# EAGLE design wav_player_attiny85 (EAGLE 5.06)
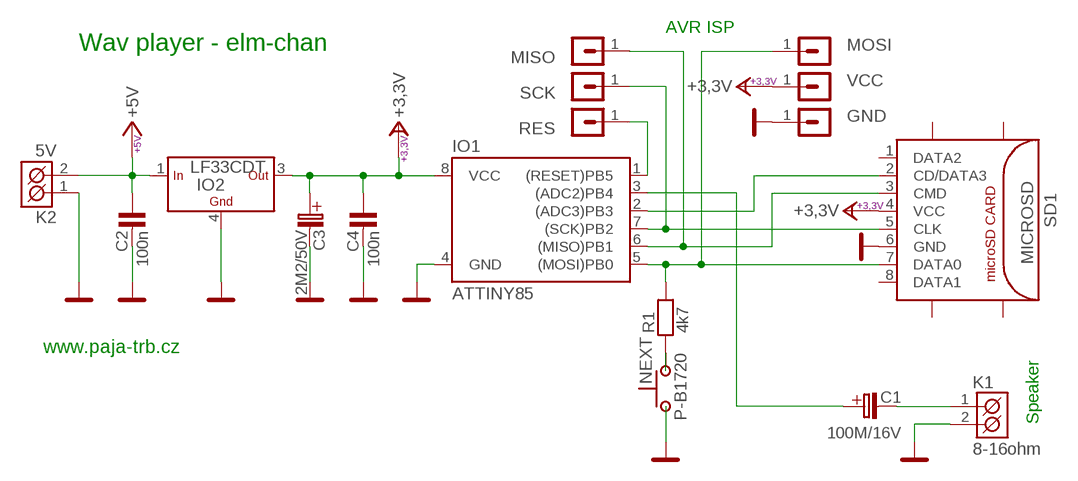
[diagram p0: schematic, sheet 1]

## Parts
C1  100M/16V  [C_EL_2,5]
C2  100n  C-KERAMIK_SMD_1206  [1206]
C3  2M2/50V  [C_EL_2]
C4  100n  C-KERAMIK_7,5  [C-7,5]
GND  S1G1_JUMP  [S1G1_JUM]
IO1  ATTINY85  ATTINY13  [SOIC08]
IO2  LF33CDT  LFDPAKDPAKC  [DPAK]
K1  8-16ohm  ARK550/2  [ARK550/2]
K2  5V  ARK550/2  [ARK550/2]
MISO  S1G1_JUMP  [S1G1_JUM]
MOSI  S1G1_JUMP  [S1G1_JUM]
NEXT  P-B1720  [P-B1720]
R1  4k7  R_SMD_1206  [1206]
RES  S1G1_JUMP  [S1G1_JUM]
SCK  S1G1_JUMP  [S1G1_JUM]
SD1  MICROSD  [MICRO_SD_CONNECTOR]
VCC  S1G1_JUMP  [S1G1_JUM]

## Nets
+3,3V: C3.C+(C_EL+) C4.1 IO1.8(VCC) IO2.3(OUT) SD1.4(VCC) VCC.1
+5V: C2.1 IO2.1(IN) K2.2(K2)
GND: C2.2 C3.C-(C_EL-) C4.2 GND.1 IO1.4(GND) IO2.4(GND) K1.2(K2) K2.1(K1) NEXT.1 NEXT.3 SD1.6(GND)
MISO: IO1.6((MISO)PB1) MISO.1 SD1.3(CMD)
MOSI: IO1.5((MOSI)PB0) MOSI.1 R1.2 SD1.7(DATA0)
N$1: C1.C-(C_EL-) K1.1(K1)
N$2: IO1.2((ADC3)PB3) SD1.2(CD/DATA3)
N$3: C1.C+(C_EL+) IO1.3((ADC2)PB4)
N$5: NEXT.2 NEXT.4 R1.1
RES: IO1.1((RESET)PB5) RES.1
SCK: IO1.7((SCK)PB2) SCK.1 SD1.5(CLK)
Unconnected: SD1.1(DATA2) SD1.8(DATA1) SD1.11(CD(1)) SD1.12(CD(2)) SD1.13(CD(3)) SD1.14(CD(4))

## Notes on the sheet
- AVR ISP
- Wav player - elm-chan
- www.paja-trb.cz
- Speaker

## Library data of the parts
C1 = #PaJa_C-el_2:100M/16V
C2 C4 = #PaJa_31:C-KERAMIK: Kondenzator - keramicky
C3 = #PaJa_C-el_2:2M2/50V
GND MISO MOSI RES SCK VCC = #PaJa_konektory:S1G1_JUMP: Radove konektory - koliky - 1x
IO1 = #PaJa_31:ATTINY13: ATMEL ATtiny 13
IO2 = #PaJa_31:LF??C: LF??C - stabilizátory low-drop výstup dle typu 1,25 - 12V
K1 K2 = #PaJa_konektory:ARK550/2: Svorkovnice - roztec 3,5mm - dvojita
NEXT = #PaJa_prepinace:P-B1720: &micro;-tlacitko
R1 = #PaJa_31:R: Rezistor
SD1 = #PaJa_konektory:MICROSD: MicroSD socked 112C-TXAR-R01 Attend technology

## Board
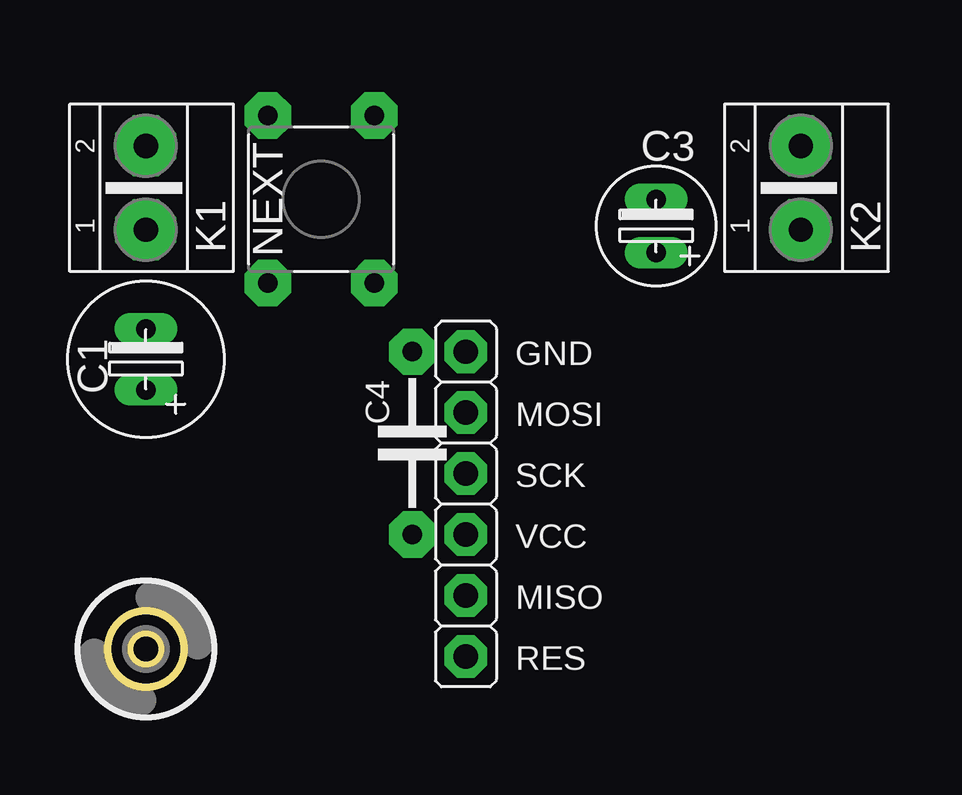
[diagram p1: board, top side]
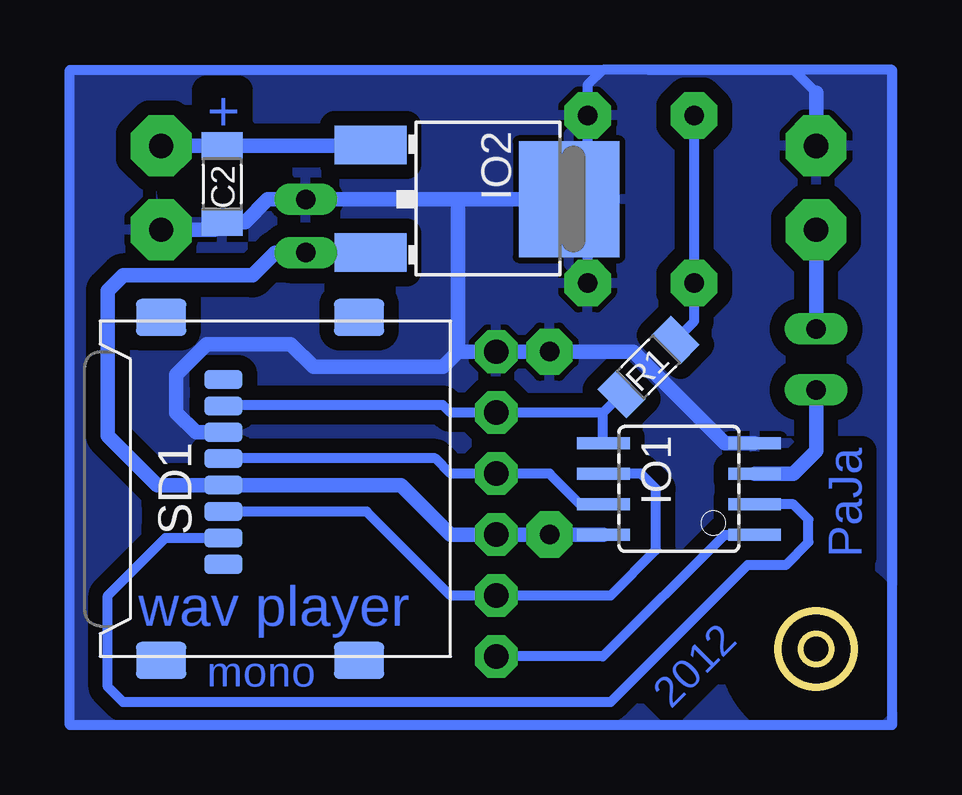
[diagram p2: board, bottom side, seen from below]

Size 3.17 x 3.17 mm. Coordinates in mm from the lower left corner, seen from the top.
Copper layers (1*16): Top 0.035mm / dielectric 1.5mm / Bottom 0.035mm
Design rules "default": minimum track width 10mil, minimum drill 24mil, track to track 8mil, track to pad 8mil, pad to pad 8mil, via to via 8mil, smd to smd 8mil, copper to edge 40mil, drill to drill 8mil, minimum pad ring 10mil, minimum via ring 8mil, stop-mask expansion 4mil, vias tented up to drill 0mil, thermal gap 10mil
bRestrict: 3 lines

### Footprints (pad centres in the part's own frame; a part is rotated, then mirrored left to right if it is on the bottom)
C_EL_2,5 = drill 0.813 pad 1.27 long: C+ -1.27,0; C- 1.27,0
1206 = smd 1.143 x 1.702: 1 -1.587,0; 2 1.587,0
C_EL_2 = drill 0.813 pad 1.27 long: C+ 0,0; C- 2.223,0
C-7,5 = drill 0.813 pad 1.93 octagon: 1 -3.81,0; 2 3.81,0
S1G1_JUM = drill 1.016 pad 1.778 octagon: 1 0,0
SOIC08 = smd 2.2 x 0.5: 1 -3.154,1.905; 2 -3.154,0.645; 3 -3.154,-0.625; 4 -3.154,-1.895; 5 3.154,-1.905; 6 3.154,-0.635; 7 3.154,0.635; 8 3.154,1.905
DPAK = smd 1.6 x 2.997: 1 -2.261,-4.928; 3 2.21,-4.928 | smd 4.826 x 4.191: 4 0,3.353
ARK550/2 = drill 1.016 pad 2.54 octagon: 1 0,0; 2 3.493,0
P-B1720 = drill 0.813 pad 1.93 octagon: 1 -3.493,-2.223; 2 -3.493,2.223; 3 3.493,-2.223; 4 3.493,2.223
MICRO_SD_CONNECTOR = smd 0.8 x 1.6: 1 -3.141,1.215; 2 -2.041,1.215; 3 -0.941,1.215; 4 0.159,1.215; 5 1.259,1.215; 6 2.359,1.215; 7 3.459,1.215; 8 4.559,1.215 | smd 1.55 x 2.1: 11 -7.144,3.81; 12 -7.144,-4.445; 13 7.144,-4.445; 14 7.144,3.81
HOLE_3,0 = hole 3.2: 0,0

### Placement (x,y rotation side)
C1  1.59,13.65 90 top  (outside the outline)
C2  26.35,20.96 270 bottom  (outside the outline)
C3  22.86,18.1 90 top  (outside the outline)
C4  12.7,10.16 90 top  (outside the outline)
GND  14.92,13.97 0 top  (outside the outline)
IO1  7.3,8.25 180 bottom  (outside the outline)
IO2  15.24,20.32 270 bottom  (outside the outline)
K1  1.59,19.05 90 top  (outside the outline)
K2  28.89,19.05 90 top  (outside the outline)
MISO  14.92,3.81 0 top  (outside the outline)
MOSI  14.92,11.43 0 top  (outside the outline)
NEXT  8.89,20.32 90 top  (outside the outline)
R1  8.57,13.33 225 bottom  (outside the outline)
RES  14.92,1.27 0 top  (outside the outline)
SCK  14.92,8.89 0 top  (outside the outline)
SD1  25.08,8.25 90 bottom  (outside the outline)
U$2  [HOLE_3,0]  1.59,1.59 0 top
VCC  14.92,6.35 0 top  (outside the outline)

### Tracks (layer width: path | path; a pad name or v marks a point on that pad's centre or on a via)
+3,3V
  Bottom 0.406: IO1.8 C4.1 | IO2.3 20.18,18.1
  Bottom 0.61: IO1.8 C4.1 VCC.1 16.83,6.35 18.89,8.41 SD1.4 29.05,8.41 31.12,10.48 31.12,16.51 30.48,17.15 25.08,17.15 24.13,18.1 C3.C+ 20.18,18.1
+5V
  Bottom 0.406: IO2.1 arc90 20.21,22.54
  Bottom 0.61: K2.2 C2.1 20.21,22.54
GND
  Bottom 0.406: IO1.4 | C2.2 arc90 26.67,19.05 | 11.11,20.32 IO2.4 | 11.11,20.32 NEXT.1 | 11.11,20.32 NEXT.3 11.11,25.08 10.48,25.72 | 8.57,25.72 -1.59,25.72 -1.59,-1.59 32.7,-1.59 32.7,25.72 10.48,25.72 | 1.59,24.76 2.54,25.72 8.57,25.72 | 8.57,25.72 10.48,25.72
  Bottom 0.61: 16.51,13.97 GND.1 C4.2 9.21,13.97 5.4,10.16 IO1.4 | 16.51,13.97 17.15,13.33 22.54,13.33 23.49,14.29 26.99,14.29 28.26,13.02 28.26,11.43 27.44,10.61 SD1.6 | 26.67,19.05 K2.1 | C2.2 25.4,19.37 24.45,20.32 C3.C- 16.51,20.32 | IO2.4 16.51,20.32 | 16.51,20.32 16.51,13.97 | 1.59,24.76 K1.2
  pour Bottom (isolate 0.61): -1.59,-1.59 32.7,-1.59 32.7,25.4 32.7,25.72 -1.59,25.72
MISO
  Bottom 0.406: IO1.6 8.89,8.89 8.25,8.25 8.25,5.72 10.16,3.81 MISO.1 16.83,3.81 20.32,7.3 26.29,7.3 SD1.3
MOSI
  Bottom 0.406: SD1.7 26.26,11.75 17.15,11.75 16.83,11.43 MOSI.1 10.48,11.43 | 10.48,10.16 IO1.5 10.48,10.18 10.48,11.43 | 10.48,11.43 R1.2
N$1
  Bottom 0.61: C1.C- K1.1
N$2
  Bottom 0.406: IO1.2 2.53,7.61 1.91,6.98 1.91,6.03 2.86,5.08 4.44,5.08 10.16,-0.63 30.48,-0.63 31.12,0 31.12,3.81 28.71,6.21 SD1.2
N$3
  Bottom 0.406: 4.14,8.89 IO1.3
  Bottom 0.61: C1.C+ 1.59,9.84 2.54,8.89 4.14,8.89
N$5
  Bottom 0.406: R1.1 6.67,15.24 NEXT.2 NEXT.4
RES
  Bottom 0.406: IO1.1 4.13,6.33 5.42,6.33 10.48,1.27 RES.1
SCK
  Bottom 0.406: SD1.5 26.29,9.53 17.46,9.53 16.83,8.89 SCK.1 12.7,8.89 11.43,7.62 IO1.7

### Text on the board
Bottom: + | PaJa | wav player | mono | 2012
